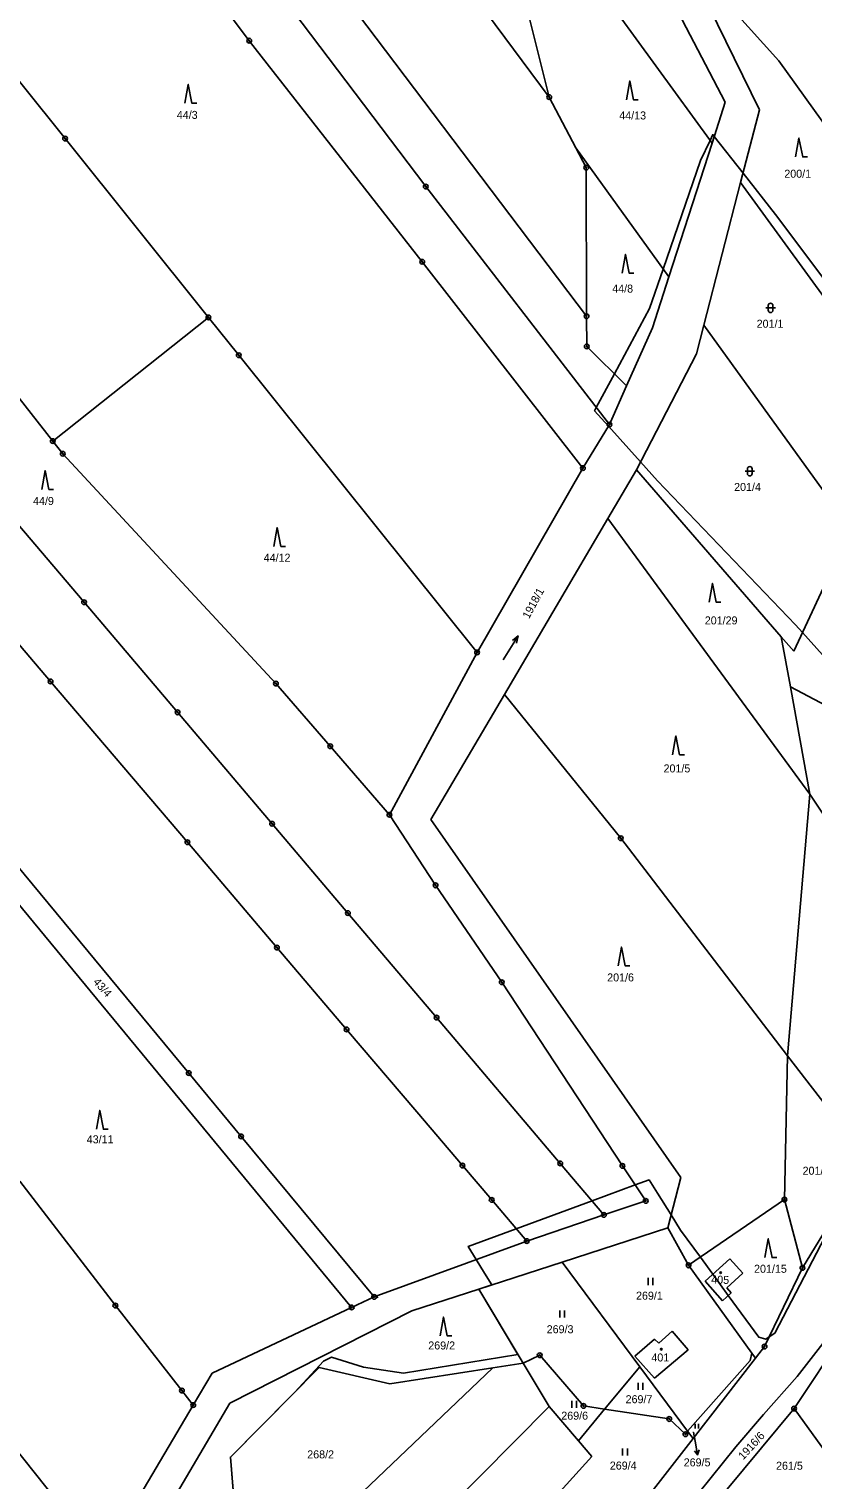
# Model space of a CAD drawing. Extents: x -445050 to -440454, y -1134563 to -1129741.
# Drawn here: x -442429.3 to -442262.8, y -1130536.2 to -1130227.9 of the extents above; entities that cross this region are included whole.
import ezdxf

# ---------------------------------------------------------------- set-up
doc = ezdxf.new("R2010")
doc.units = 0
for name, color, linetype in [('Vrstva 1', 7, 'Continuous'), ('Vrstva 16', 7, 'Continuous'), ('Vrstva 18', 7, 'Continuous'), ('Vrstva 19', 7, 'Continuous'), ('Vrstva 24', 7, 'Continuous'), ('Vrstva 25', 7, 'Continuous'), ('Vrstva 3', 7, 'Continuous'), ('Vrstva 37', 7, 'Continuous'), ('Vrstva 5', 7, 'Continuous'), ('Vrstva 52', 7, 'Continuous'), ('Vrstva 6', 7, 'Continuous')]:
    doc.layers.add(name, color=color, linetype=linetype)

msp = doc.modelspace()

# ---------------------------------------------------------------- linework, layer by layer
at = {"layer": 'Vrstva 1'}
for p, q in [((-442320.82, -1130509.72), (-442324.36, -1130511.4)), ((-442311.53, -1130520.49), (-442320.82, -1130509.72)), ((-442307.04, -1130521.18), (-442299.56, -1130512.16)), ((-442307.04, -1130521.18), (-442312.59, -1130527.88)), ((-442307.04, -1130521.18), (-442311.53, -1130520.49)), ((-442293.29, -1130523.27), (-442307.04, -1130521.18)), ((-442289.85, -1130526.51), (-442293.29, -1130523.27)), ((-442289.41, -1130525.86), (-442289.85, -1130526.51))]:
    msp.add_line(p, q, dxfattribs=at)
for points in [[(-442410.78, -1130174.44), (-442345.04, -1130261.4)], [(-442382.53, -1130230.41), (-442418.66, -1130182.12)], [(-442360.56, -1130186.13), (-442318.79, -1130242.39)], [(-442308, -1130192.55), (-442281.39, -1130243.51)], [(-442329.25, -1130200.73), (-442318.79, -1130242.39)], [(-442458.57, -1130205.18), (-442421.66, -1130251.2)], [(-442310.85, -1130288.97), (-442371.85, -1130208.3)], [(-442290.22, -1130212.23), (-442274.14, -1130245.08)], [(-442345.78, -1130277.38), (-442382.53, -1130230.41)], [(-442318.79, -1130242.39), (-442313.15, -1130253.17)], [(-442284.19, -1130252.17), (-442281.39, -1130243.51)], [(-442278.12, -1130260.52), (-442274.14, -1130245.08)], [(-442421.66, -1130251.2), (-442391.19, -1130289.21)], [(-442313.15, -1130253.17), (-442310.94, -1130257.39)], [(-442293.37, -1130280.59), (-442284.19, -1130252.17)], [(-442310.94, -1130257.39), (-442310.85, -1130288.97)], [(-442285.95, -1130290.87), (-442278.12, -1130260.52)], [(-442278.12, -1130260.52), (-442259.71, -1130285.84)], [(-442345.04, -1130261.4), (-442306, -1130311.98)], [(-442311.63, -1130321.24), (-442345.78, -1130277.38)], [(-442296.87, -1130291.4), (-442293.37, -1130280.59)], [(-442424.28, -1130315.5), (-442442.78, -1130291.97)], [(-442424.28, -1130315.5), (-442391.19, -1130289.21)], [(-442391.19, -1130289.21), (-442384.75, -1130297.24)], [(-442310.85, -1130288.97), (-442310.83, -1130295.38)], [(-442302.34, -1130303.74), (-442296.87, -1130291.4)], [(-442287.52, -1130296.95), (-442285.95, -1130290.87)], [(-442285.95, -1130290.87), (-442254.74, -1130334.14)], [(-442384.75, -1130297.24), (-442334.12, -1130360.38)], [(-442310.83, -1130295.38), (-442302.34, -1130303.74)], [(-442287.52, -1130296.95), (-442300.23, -1130321.59)], [(-442306, -1130311.98), (-442302.34, -1130303.74)], [(-442306, -1130311.98), (-442311.63, -1130321.24)], [(-442422.17, -1130318.19), (-442424.28, -1130315.5)], [(-442417.63, -1130349.73), (-442443.44, -1130319.37)], [(-442376.88, -1130367.01), (-442422.17, -1130318.19)], [(-442311.63, -1130321.24), (-442334.12, -1130360.38)], [(-442306.32, -1130331.94), (-442300.23, -1130321.59)], [(-442300.23, -1130321.59), (-442269.48, -1130357.09)], [(-442328.32, -1130369.31), (-442306.32, -1130331.94)], [(-442443.58, -1130344.44), (-442424.75, -1130366.56)], [(-442260.54, -1130346.62), (-442266.83, -1130360.15)], [(-442397.77, -1130373.12), (-442417.63, -1130349.73)], [(-442269.48, -1130357.09), (-442266.83, -1130360.15)], [(-442269.48, -1130357.09), (-442267.55, -1130367.73)], [(-442334.12, -1130360.38), (-442352.76, -1130394.88)], [(-442466.77, -1130363.62), (-442395.39, -1130449.77)], [(-442470.57, -1130366.64), (-442360.77, -1130499.58)], [(-442424.75, -1130366.56), (-442395.68, -1130400.74)], [(-442365.32, -1130380.33), (-442376.88, -1130367.01)], [(-442243.5, -1130380.36), (-442267.55, -1130367.73)], [(-442267.55, -1130367.73), (-442263.42, -1130390.54)], [(-442343.97, -1130395.9), (-442328.32, -1130369.31)], [(-442328.32, -1130369.31), (-442303.59, -1130399.87)], [(-442377.68, -1130396.8), (-442397.77, -1130373.12)], [(-442430.79, -1130742.31), (-442424.62, -1130733.2), (-442415.82, -1130720.62), (-442409.44, -1130711.5), (-442393.93, -1130688.86), (-442358.25, -1130635.86), (-442352.69, -1130627.61), (-442332.86, -1130599.66), (-442309.46, -1130567.56), (-442303.89, -1130560.33), (-442293.28, -1130546.91), (-442286.99, -1130538.97), (-442279.11, -1130529.2), (-442273.28, -1130522.3), (-442266.1, -1130514.22), (-442252.71, -1130497.03), (-442249.64, -1130492.6), (-442243.06, -1130482.81), (-442233.55, -1130466.59), (-442229.34, -1130457.62), (-442222.85, -1130440.58), (-442219.54, -1130431.16), (-442202.59, -1130378.37)], [(-442352.76, -1130394.88), (-442365.32, -1130380.33)], [(-442263.42, -1130390.54), (-442268.18, -1130446.12)], [(-442263.42, -1130390.54), (-442249.89, -1130410.74)], [(-442361.57, -1130415.78), (-442377.68, -1130396.8)], [(-442352.76, -1130394.88), (-442342.95, -1130409.88)], [(-442343.97, -1130395.9), (-442290.81, -1130471.99)], [(-442303.59, -1130399.87), (-442268.18, -1130446.12)], [(-442395.68, -1130400.74), (-442376.65, -1130423.1)], [(-442342.95, -1130409.88), (-442328.88, -1130430.47)], [(-442342.73, -1130437.99), (-442361.57, -1130415.78)], [(-442376.65, -1130423.1), (-442361.84, -1130440.51)], [(-442328.88, -1130430.47), (-442303.24, -1130469.5)], [(-442316.44, -1130468.96), (-442342.73, -1130437.99)], [(-442361.84, -1130440.51), (-442346.95, -1130458.01)], [(-442268.18, -1130446.12), (-442268.82, -1130476.66)], [(-442268.18, -1130446.12), (-442251.02, -1130468.25)], [(-442384.25, -1130463.23), (-442395.39, -1130449.77)], [(-442346.95, -1130458.01), (-442337.23, -1130469.44)], [(-442355.99, -1130497.33), (-442384.25, -1130463.23)], [(-442337.23, -1130469.44), (-442331.02, -1130476.73)], [(-442307.16, -1130479.9), (-442316.44, -1130468.96)], [(-442303.24, -1130469.5), (-442298.3, -1130476.92)], [(-442251.02, -1130468.25), (-442264.98, -1130491.16)], [(-442410.98, -1130499.18), (-442431.25, -1130472.71)], [(-442290.81, -1130471.99), (-442293.61, -1130482.67)], [(-442331.02, -1130476.73), (-442323.58, -1130485.48)], [(-442298.3, -1130476.92), (-442307.16, -1130479.9)], [(-442289.19, -1130490.62), (-442268.82, -1130476.66)], [(-442268.82, -1130476.66), (-442264.98, -1130491.16)], [(-442307.16, -1130479.9), (-442323.58, -1130485.48)], [(-442293.61, -1130482.67), (-442316.03, -1130489.94)], [(-442289.19, -1130490.62), (-442293.61, -1130482.67)], [(-442323.58, -1130485.48), (-442355.99, -1130497.33)], [(-442280.45, -1130489.24), (-442285.65, -1130493.98)], [(-442277.64, -1130492.31), (-442280.45, -1130489.24)], [(-442316.03, -1130489.94), (-442333.77, -1130495.69)], [(-442299.56, -1130512.16), (-442316.03, -1130489.94)], [(-442275.74, -1130509.27), (-442289.19, -1130490.62)], [(-442281.07, -1130495.41), (-442277.64, -1130492.31)], [(-442264.98, -1130491.16), (-442273.05, -1130507.88)], [(-442285.65, -1130493.98), (-442282, -1130498.19)], [(-442280.13, -1130496.45), (-442281.07, -1130495.41)], [(-442355.99, -1130497.33), (-442360.77, -1130499.58)], [(-442333.77, -1130495.69), (-442347.99, -1130500.3)], [(-442333.77, -1130495.69), (-442324.36, -1130511.4)], [(-442282, -1130498.19), (-442280.13, -1130496.45)], [(-442396.83, -1130517.23), (-442410.98, -1130499.18)], [(-442360.77, -1130499.58), (-442390.39, -1130513.5)], [(-442386.66, -1130519.88), (-442347.99, -1130500.3)], [(-442295.48, -1130507.13), (-442292.67, -1130504.59)], [(-442292.67, -1130504.59), (-442289.27, -1130508.55)], [(-442300.63, -1130509.94), (-442296.39, -1130506.28)], [(-442296.39, -1130506.28), (-442295.48, -1130507.13)], [(-442256.17, -1130505.2), (-442266.77, -1130521.05)], [(-442296.44, -1130514.58), (-442300.63, -1130509.94)], [(-442289.27, -1130508.55), (-442296.44, -1130514.58)], [(-442276.11, -1130510.84), (-442289.41, -1130525.86)], [(-442288.24, -1130527.45), (-442274.96, -1130510.35)], [(-442276.11, -1130510.84), (-442275.74, -1130509.27)], [(-442274.96, -1130510.35), (-442275.74, -1130509.27)], [(-442274.96, -1130510.35), (-442273.05, -1130507.88)], [(-442330.75, -1130512.4), (-442398.11, -1130576.64)], [(-442390.39, -1130513.5), (-442394.42, -1130520.31)], [(-442367.7, -1130512.32), (-442386.53, -1130531.38)], [(-442352.69, -1130515.83), (-442367.7, -1130512.32)], [(-442352.69, -1130515.83), (-442330.75, -1130512.4)], [(-442330.75, -1130512.4), (-442324.36, -1130511.4)], [(-442324.36, -1130511.4), (-442318.84, -1130520.61)], [(-442289.41, -1130525.86), (-442299.56, -1130512.16)], [(-442420.53, -1130544.24), (-442443.15, -1130515.88)], [(-442386.66, -1130519.88), (-442409.55, -1130558.76)], [(-442394.42, -1130520.31), (-442396.83, -1130517.23)], [(-442394.42, -1130520.31), (-442413.65, -1130552.86)], [(-442355.44, -1130557.59), (-442318.84, -1130520.61)], [(-442312.59, -1130527.88), (-442318.84, -1130520.61)], [(-442284.45, -1130542.38), (-442266.77, -1130521.05)], [(-442266.77, -1130521.05), (-442249.1, -1130545.46)], [(-442288.24, -1130527.45), (-442289.41, -1130525.86)], [(-442309.71, -1130531.24), (-442312.59, -1130527.88)], [(-442305.09, -1130549.12), (-442288.24, -1130527.45)], [(-442386.53, -1130531.38), (-442385.24, -1130547.32)], [(-442316.48, -1130538.67), (-442309.71, -1130531.24)]]:
    msp.add_lwpolyline(points, dxfattribs=at)
at = {"layer": 'Vrstva 16'}
msp.add_line((-442287.81, -1130527.95), (-442287.28, -1130530.9), dxfattribs=at)
for points in [[(-442288.15, -1130526.09), (-442287.81, -1130527.95)], [(-442286.96, -1130529.83), (-442287.28, -1130530.9), (-442287.95, -1130530.01)]]:
    msp.add_lwpolyline(points, dxfattribs=at)
at = {"layer": 'Vrstva 24'}
for centre, radius in [((-442382.53, -1130230.41), 0.5), ((-442382.53, -1130230.41), 0.1), ((-442318.79, -1130242.39), 0.5), ((-442318.79, -1130242.39), 0.1), ((-442421.66, -1130251.2), 0.5), ((-442421.66, -1130251.2), 0.1), ((-442310.94, -1130257.39), 0.5), ((-442310.94, -1130257.39), 0.1), ((-442345.04, -1130261.4), 0.5), ((-442345.04, -1130261.4), 0.1), ((-442345.78, -1130277.38), 0.5), ((-442345.78, -1130277.38), 0.1), ((-442391.19, -1130289.21), 0.5), ((-442310.85, -1130288.97), 0.5), ((-442310.85, -1130288.97), 0.1), ((-442391.19, -1130289.21), 0.1), ((-442310.83, -1130295.38), 0.5), ((-442384.75, -1130297.24), 0.5), ((-442384.75, -1130297.24), 0.1), ((-442310.83, -1130295.38), 0.1), ((-442306, -1130311.98), 0.5), ((-442306, -1130311.98), 0.1), ((-442424.28, -1130315.5), 0.5), ((-442424.28, -1130315.5), 0.1), ((-442422.17, -1130318.19), 0.5), ((-442422.17, -1130318.19), 0.1), ((-442311.63, -1130321.24), 0.5), ((-442311.63, -1130321.24), 0.1), ((-442417.63, -1130349.73), 0.5), ((-442417.63, -1130349.73), 0.1), ((-442334.12, -1130360.38), 0.5), ((-442334.12, -1130360.38), 0.1), ((-442424.75, -1130366.56), 0.5), ((-442424.75, -1130366.56), 0.1), ((-442376.88, -1130367.01), 0.5), ((-442376.88, -1130367.01), 0.1), ((-442397.77, -1130373.12), 0.5), ((-442397.77, -1130373.12), 0.1), ((-442365.32, -1130380.33), 0.5), ((-442365.32, -1130380.33), 0.1), ((-442377.68, -1130396.8), 0.5), ((-442377.68, -1130396.8), 0.1), ((-442352.76, -1130394.88), 0.5), ((-442352.76, -1130394.88), 0.1), ((-442303.59, -1130399.87), 0.5), ((-442303.59, -1130399.87), 0.1), ((-442395.68, -1130400.74), 0.5), ((-442395.68, -1130400.74), 0.1), ((-442342.95, -1130409.88), 0.5), ((-442342.95, -1130409.88), 0.1), ((-442361.57, -1130415.78), 0.5), ((-442361.57, -1130415.78), 0.1), ((-442376.65, -1130423.1), 0.5), ((-442376.65, -1130423.1), 0.1), ((-442328.88, -1130430.47), 0.5), ((-442328.88, -1130430.47), 0.1), ((-442342.73, -1130437.99), 0.5), ((-442342.73, -1130437.99), 0.1), ((-442361.84, -1130440.51), 0.5), ((-442361.84, -1130440.51), 0.1), ((-442395.39, -1130449.77), 0.5), ((-442395.39, -1130449.77), 0.1), ((-442384.25, -1130463.23), 0.5), ((-442384.25, -1130463.23), 0.1), ((-442337.23, -1130469.44), 0.5), ((-442337.23, -1130469.44), 0.1), ((-442316.44, -1130468.96), 0.5), ((-442316.44, -1130468.96), 0.1), ((-442303.24, -1130469.5), 0.5), ((-442303.24, -1130469.5), 0.1), ((-442331.02, -1130476.73), 0.5), ((-442331.02, -1130476.73), 0.1), ((-442298.3, -1130476.92), 0.5), ((-442298.3, -1130476.92), 0.1), ((-442268.82, -1130476.66), 0.5), ((-442268.82, -1130476.66), 0.1), ((-442307.16, -1130479.9), 0.5), ((-442307.16, -1130479.9), 0.1), ((-442323.58, -1130485.48), 0.5), ((-442323.58, -1130485.48), 0.1), ((-442289.19, -1130490.62), 0.5), ((-442289.19, -1130490.62), 0.1), ((-442264.98, -1130491.16), 0.5), ((-442264.98, -1130491.16), 0.1), ((-442355.99, -1130497.33), 0.5), ((-442355.99, -1130497.33), 0.1), ((-442410.98, -1130499.18), 0.5), ((-442410.98, -1130499.18), 0.1), ((-442360.77, -1130499.58), 0.5), ((-442360.77, -1130499.58), 0.1), ((-442273.05, -1130507.88), 0.5), ((-442273.05, -1130507.88), 0.1), ((-442320.82, -1130509.72), 0.5), ((-442320.82, -1130509.72), 0.1), ((-442396.83, -1130517.23), 0.5), ((-442396.83, -1130517.23), 0.1), ((-442394.42, -1130520.31), 0.5), ((-442311.53, -1130520.49), 0.5), ((-442394.42, -1130520.31), 0.1), ((-442311.53, -1130520.49), 0.1), ((-442293.29, -1130523.27), 0.5), ((-442293.29, -1130523.27), 0.1), ((-442266.77, -1130521.05), 0.5), ((-442266.77, -1130521.05), 0.1), ((-442289.85, -1130526.51), 0.5), ((-442289.85, -1130526.51), 0.1)]:
    msp.add_circle(centre, radius, dxfattribs=at)
at = {"layer": 'Vrstva 25'}
for p, q in [((-442272.75, -1130287.18), (-442270.75, -1130287.18)), ((-442272.25, -1130287.68), (-442272.25, -1130286.68)), ((-442271.25, -1130286.68), (-442271.25, -1130287.68)), ((-442277.17, -1130321.9), (-442275.17, -1130321.9)), ((-442276.67, -1130322.4), (-442276.67, -1130321.4)), ((-442275.67, -1130321.4), (-442275.67, -1130322.4)), ((-442297.76, -1130494.81), (-442297.76, -1130493.31)), ((-442296.76, -1130494.81), (-442296.76, -1130493.31)), ((-442316.52, -1130501.73), (-442316.52, -1130500.23)), ((-442315.52, -1130501.73), (-442315.52, -1130500.23)), ((-442299.9, -1130517.07), (-442299.9, -1130515.57)), ((-442298.9, -1130517.07), (-442298.9, -1130515.57)), ((-442314.02, -1130520.89), (-442314.02, -1130519.39)), ((-442313.02, -1130520.89), (-442313.02, -1130519.39)), ((-442287.76, -1130525.3), (-442287.76, -1130524.29)), ((-442287.09, -1130525.3), (-442287.09, -1130524.29)), ((-442303.19, -1130531.04), (-442303.19, -1130529.54)), ((-442302.19, -1130531.04), (-442302.19, -1130529.54))]:
    msp.add_line(p, q, dxfattribs=at)
for points in [[(-442302.4, -1130242.97), (-442301.7, -1130238.97), (-442300.9, -1130242.97), (-442299.9, -1130242.97)], [(-442396.2, -1130243.72), (-442395.5, -1130239.72), (-442394.7, -1130243.72), (-442393.7, -1130243.72)], [(-442266.43, -1130255.11), (-442265.73, -1130251.11), (-442264.93, -1130255.11), (-442263.93, -1130255.11)], [(-442303.3, -1130279.84), (-442302.6, -1130275.84), (-442301.8, -1130279.84), (-442300.8, -1130279.84)], [(-442426.6, -1130325.75), (-442425.9, -1130321.75), (-442425.1, -1130325.75), (-442424.1, -1130325.75)], [(-442377.3, -1130337.87), (-442376.6, -1130333.87), (-442375.8, -1130337.87), (-442374.8, -1130337.87)], [(-442284.82, -1130349.72), (-442284.12, -1130345.72), (-442283.32, -1130349.72), (-442282.32, -1130349.72)], [(-442328.59, -1130361.97), (-442325.41, -1130356.89), (-442326.63, -1130357.89)], [(-442325.41, -1130356.89), (-442325.78, -1130358.42)], [(-442292.58, -1130382.12), (-442291.88, -1130378.12), (-442291.08, -1130382.12), (-442290.08, -1130382.12)], [(-442304.15, -1130427), (-442303.45, -1130423), (-442302.65, -1130427), (-442301.65, -1130427)], [(-442415.01, -1130461.69), (-442414.31, -1130457.69), (-442413.51, -1130461.69), (-442412.51, -1130461.69)], [(-442272.95, -1130488.98), (-442272.25, -1130484.98), (-442271.45, -1130488.98), (-442270.45, -1130488.98)], [(-442341.96, -1130505.63), (-442341.26, -1130501.63), (-442340.46, -1130505.63), (-442339.46, -1130505.63)]]:
    msp.add_lwpolyline(points, dxfattribs=at)
for centre in [(-442282.37, -1130492.19), (-442294.99, -1130508.44)]:
    msp.add_circle(centre, 0.175, dxfattribs=at)
for centre, start, end in [((-442271.75, -1130286.68), 0, 180), ((-442271.75, -1130287.68), 180, 0), ((-442276.17, -1130321.4), 0, 180), ((-442276.17, -1130322.4), 180, 0)]:
    msp.add_arc(centre, 0.5, start, end, dxfattribs=at)
at = {"layer": 'Vrstva 3'}
for points in [[(-442280.45, -1130489.24), (-442285.65, -1130493.98)], [(-442277.64, -1130492.31), (-442280.45, -1130489.24)], [(-442281.07, -1130495.41), (-442277.64, -1130492.31)], [(-442285.65, -1130493.98), (-442282, -1130498.19)], [(-442280.13, -1130496.45), (-442281.07, -1130495.41)], [(-442282, -1130498.19), (-442280.13, -1130496.45)], [(-442295.48, -1130507.13), (-442292.67, -1130504.59)], [(-442292.67, -1130504.59), (-442289.27, -1130508.55)], [(-442300.63, -1130509.94), (-442296.39, -1130506.28)], [(-442296.39, -1130506.28), (-442295.48, -1130507.13)], [(-442296.44, -1130514.58), (-442300.63, -1130509.94)], [(-442289.27, -1130508.55), (-442296.44, -1130514.58)]]:
    msp.add_lwpolyline(points, dxfattribs=at)
at = {"layer": 'Vrstva 37'}
for centre in [(-442282.37, -1130492.19), (-442294.99, -1130508.44)]:
    msp.add_circle(centre, 0.175, dxfattribs=at)
at = {"layer": 'Vrstva 5'}
msp.add_lwpolyline([(-442355.19, -1130497.51), (-442355.49, -1130497.15)], dxfattribs=at)
at = {"layer": 'Vrstva 52'}
for points in [[(-442247.33, -1130375.82), (-442264.97, -1130356.15), (-442266.43, -1130354.53), (-442295.76, -1130323.91), (-442299.37, -1130319.91), (-442306.2, -1130312.32), (-442309.16, -1130309.03), (-442308.79, -1130308.36), (-442304.93, -1130301.19), (-442297.46, -1130287.35), (-442294.57, -1130278.93), (-442286.62, -1130255.88), (-442284.61, -1130251.59), (-442284.04, -1130250.36), (-442283.73, -1130250.75), (-442277.61, -1130258.54), (-442270.68, -1130267.36), (-442259.58, -1130282.17)], [(-442385.25, -1130547.17), (-442386.53, -1130531.38), (-442372.85, -1130517.54), (-442366.77, -1130511), (-442365.07, -1130510.15), (-442358.27, -1130512.27), (-442349.76, -1130513.55), (-442325.44, -1130509.6), (-442333.77, -1130495.69), (-442331.01, -1130494.8), (-442332.54, -1130492.29), (-442334.31, -1130489.4), (-442336.01, -1130486.62), (-442325.81, -1130482.86), (-442309.69, -1130476.92), (-442300.54, -1130473.55), (-442297.58, -1130472.46), (-442295.76, -1130475.28), (-442292.89, -1130479.91), (-442290.88, -1130483.15), (-442286.68, -1130488.9), (-442284.05, -1130492.52), (-442280.75, -1130497.03), (-442274.29, -1130505.9), (-442272.8, -1130506.32), (-442272.06, -1130505.82), (-442270.89, -1130505.05), (-442255.78, -1130476.07)]]:
    msp.add_lwpolyline(points, dxfattribs=at)
at = {"layer": 'Vrstva 6'}
for points in [[(-442332.02, -1130186.4), (-442284.19, -1130252.17)], [(-442290.22, -1130212.23), (-442270, -1130234.69)], [(-442270, -1130234.69), (-442255.19, -1130255.32)], [(-442313.15, -1130253.17), (-442293.37, -1130280.59)], [(-442306.32, -1130331.94), (-442263.42, -1130390.54)]]:
    msp.add_lwpolyline(points, dxfattribs=at)

# ---------------------------------------------------------------- texts
at = {"layer": 'Vrstva 16'}
msp.add_text('1916/6', height=1.7, rotation=47.3141, dxfattribs=at).set_placement((-442277.57, -1130532.06))
msp.add_text('269/5', height=1.7, dxfattribs=at).set_placement((-442290.22, -1130533.34))
at = {"layer": 'Vrstva 18'}
for s, height, p in [('44/3', 1.7, (-442397.92, -1130247.03)), ('44/13', 1.7, (-442303.91, -1130247.15)), ('200/1', 1.7, (-442268.84, -1130259.53)), ('44/8', 1.7, (-442305.4, -1130283.94)), ('201/1', 1.7, (-442274.72, -1130291.4)), ('201/4', 1.7, (-442279.51, -1130326.09)), ('44/9', 1.7, (-442428.47, -1130329.06)), ('44/12', 1.7, (-442379.46, -1130341.12)), ('201/29', 1.7, (-442285.74, -1130354.44)), ('201/5', 1.7, (-442294.5, -1130385.89)), ('201/6', 1.7, (-442306.48, -1130430.3)), ('43/11', 1.7, (-442417.06, -1130464.7)), ('201/26', 1.7, (-442264.96, -1130471.37)), ('201/15', 1.7, (-442275.27, -1130492.2)), ('269/1', 1.7, (-442300.35, -1130497.92)), ('269/3', 1.7, (-442319.33, -1130505.05)), ('269/2', 1.7, (-442344.49, -1130508.5)), ('269/7', 1.7, (-442302.56, -1130519.92)), ('269/6', 1.7, (-442316.23, -1130523.42)), ('269/5', 0.1, (-442288.34, -1130526.09)), ('268/2', 1.7, (-442370.21, -1130531.64)), ('269/4', 1.7, (-442305.92, -1130534.02)), ('261/5', 1.7, (-442270.6, -1130534.05))]:
    msp.add_text(s, height=height, dxfattribs=at).set_placement(p)
for s, rotation, p in [('1918/1', 61.6248, (-442323.1, -1130353.39)), ('43/4', 311.8104, (-442415.81, -1130430.5))]:
    msp.add_text(s, height=1.7, rotation=rotation, dxfattribs=at).set_placement(p)
at = {"layer": 'Vrstva 19'}
msp.add_text('405', height=1.7, rotation=357.7456, dxfattribs=at).set_placement((-442284.39, -1130494.45))
msp.add_text('401', height=1.7, dxfattribs=at).set_placement((-442297.09, -1130511.05))

doc.saveas('drawing.dxf')
